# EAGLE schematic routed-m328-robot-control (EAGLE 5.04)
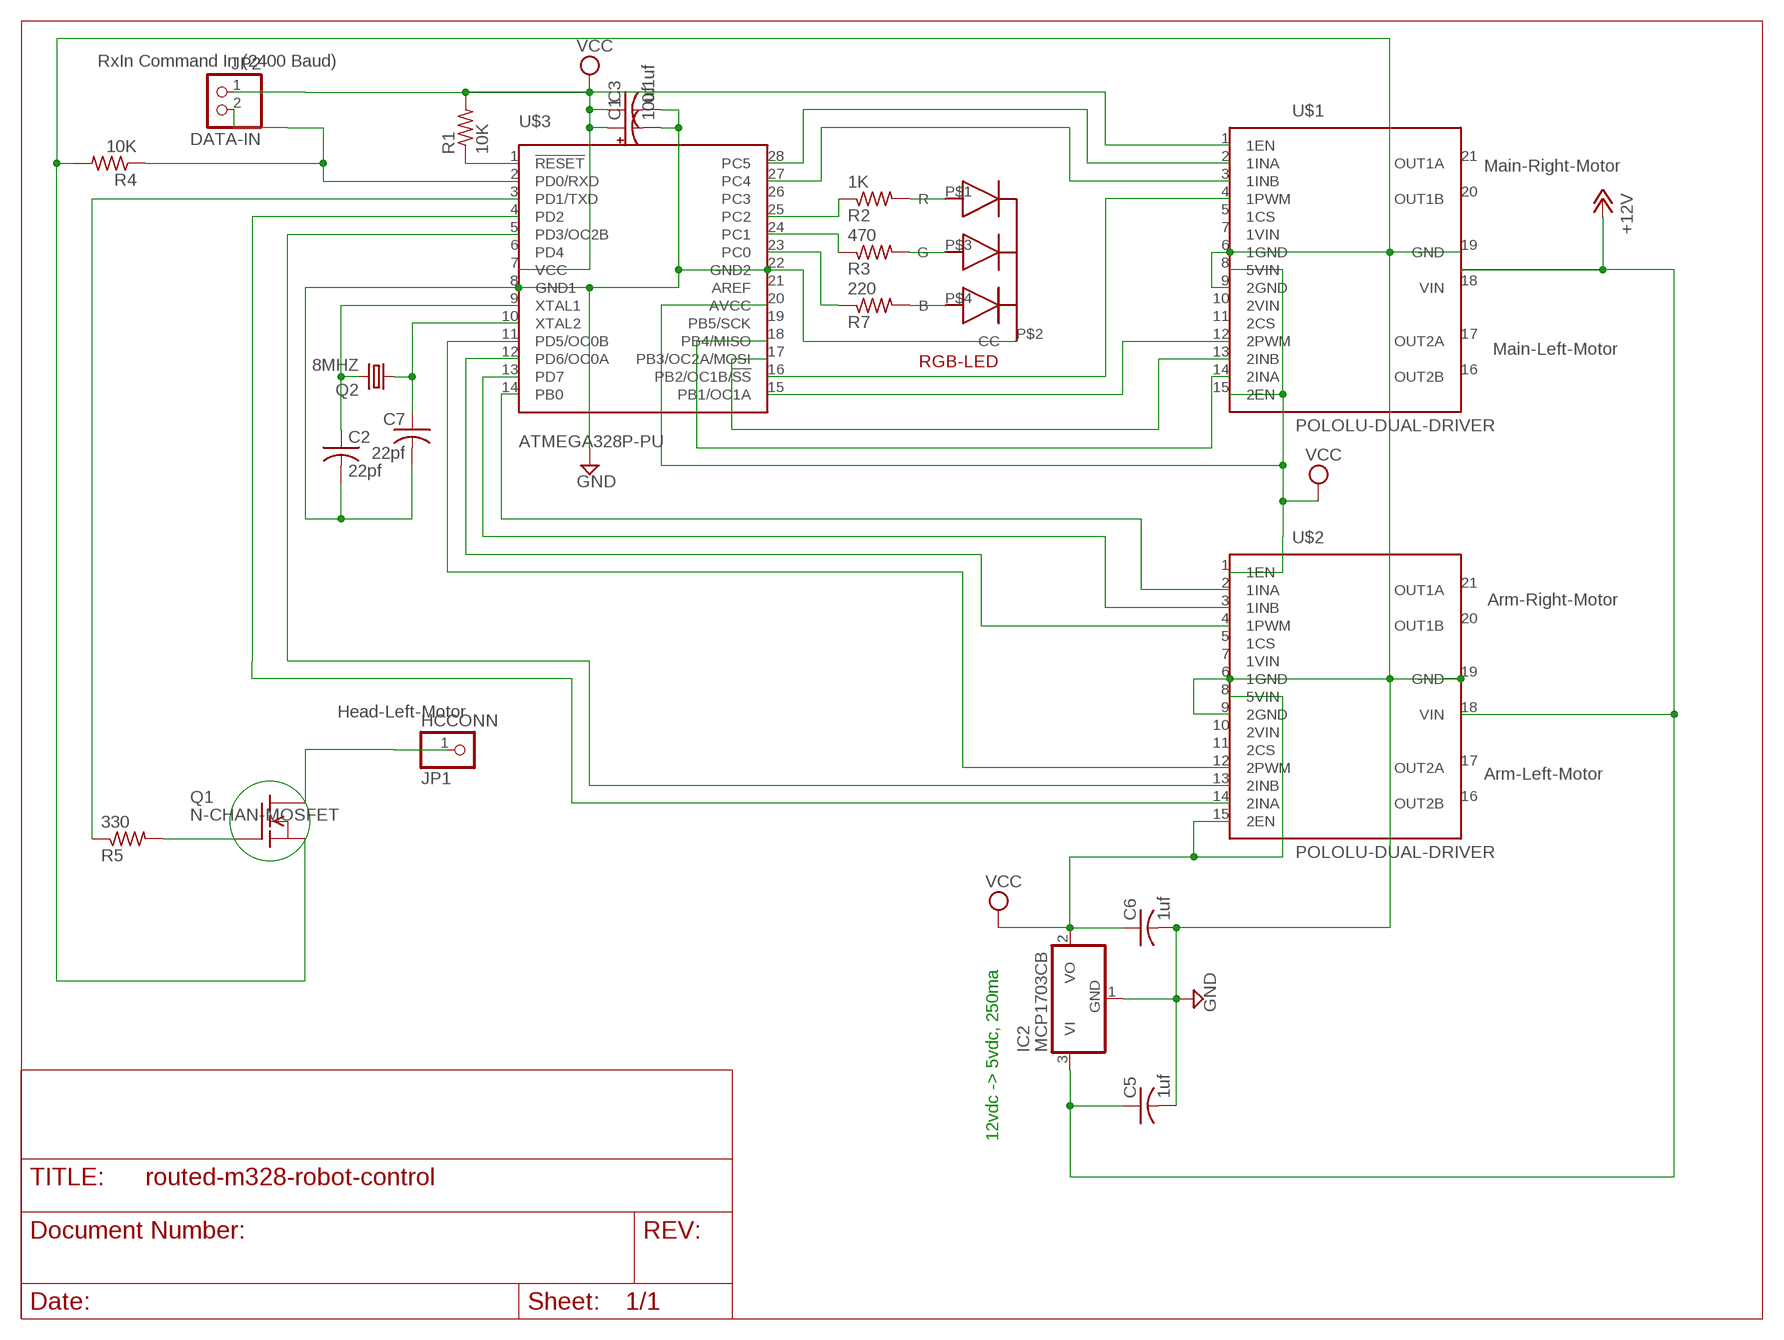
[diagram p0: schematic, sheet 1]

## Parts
C1  10uf  CPOL-USE1.8-4  [E1,8-4]
C2  22pf  C-US025-025X050  [C025-025X050]
C3  0.1uf  C-US025-025X050  [C025-025X050]
C5  1uf  C-US025-025X050  [C025-025X050]
C6  1uf  C-US025-025X050  [C025-025X050]
C7  22pf  C-US025-025X050  [C025-025X050]
IC2  MCP1703CB  [SOT23]
JP1  HCCONN  PINHD-1X1  [1X01]
JP2  DATA-IN  PINHD-1X2  [1X02]
Q1  N-CHAN-MOSFET  SUP75N06-08  [TO220]
Q2  8MHZ  CRYSTALHC49U-V  [HC49U-V]
R1  10K  R-US_0204/5  [0204/5]
R2  1K  R-US_0204/5  [0204/5]
R3  470  R-US_0204/5  [0204/5]
R4  10K  R-US_0204/5  [0204/5]
R5  330  R-US_0204/5  [0204/5]
R7  220  R-US_0204/5  [0204/5]
RGB-LED  RGB-LED-5MM  [RGB-LED-5MM]
U$1  POLOLU-DUAL-DRIVER  [POLOLU-DUAL-DRIVER]
U$2  POLOLU-DUAL-DRIVER  [POLOLU-DUAL-DRIVER]
U$3  ATMEGA328P-PU  [DIL28-3]

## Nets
+12V: C5.1 IC2.3(VI) U$2.18(VIN)
GND: C1.- C2.2 C3.2 C5.2 C6.2 C7.2 IC2.1(GND) Q1.3(S) R4.2 RGB-LED.P$2(CC) U$1.6(1GND) U$1.9(2GND) U$1.19(GND) U$2.6(1GND) U$2.9(2GND) U$2.19(GND) U$3.8(GND1) U$3.22(GND2)
N$1: R1.1 U$3.1(!RESET)
N$2: R5.1 U$3.3(PD1/TXD)
N$3: JP2.2 R4.1 U$3.2(PD0/RXD)
N$4: R7.2 RGB-LED.P$4(B)
N$5: R7.1 U$3.23(PC0)
N$6: U$2.3(1INB) U$3.13(PD7)
N$7: U$2.13(2INB) U$3.5(PD3/OC2B)
N$8: R3.2 RGB-LED.P$3(G)
N$9: R2.2 RGB-LED.P$1(R)
N$10: U$1.4(1PWM) U$3.16(PB2/OC1B/!SS)
N$11: JP1.1 Q1.2(D)
N$12: U$1.12(2PWM) U$3.15(PB1/OC1A)
N$13: U$2.12(2PWM) U$3.11(PD5/OC0B)
N$14: U$1.14(2INA) U$3.18(PB4/MISO)
N$15: U$2.4(1PWM) U$3.12(PD6/OC0A)
N$16: Q1.1(G) R5.2
N$17: R3.1 U$3.24(PC1)
N$18: R2.1 U$3.25(PC2)
N$19: U$1.13(2INB) U$3.17(PB3/OC2A/MOSI)
N$20: C7.1 Q2.1 U$3.10(XTAL2)
N$21: U$1.2(1INA) U$3.28(PC5)
N$22: U$1.3(1INB) U$3.27(PC4)
N$25: C2.1 Q2.2 U$3.9(XTAL1)
N$26: U$2.14(2INA) U$3.4(PD2)
N$54: U$2.2(1INA) U$3.14(PB0)
VCC: C1.+ C3.1 C6.1 IC2.2(VO) JP2.1 R1.2 U$1.1(1EN) U$1.8(5VIN) U$1.15(2EN) U$2.1(1EN) U$2.8(5VIN) U$2.15(2EN) U$3.7(VCC) U$3.20(AVCC)
Unconnected: U$1.5(1CS) U$1.7(1VIN) U$1.10(2VIN) U$1.11(2CS) U$1.16(OUT2B) U$1.17(OUT2A) U$1.18(VIN) U$1.20(OUT1B) U$1.21(OUT1A) U$2.5(1CS) U$2.7(1VIN) U$2.10(2VIN) U$2.11(2CS) U$2.16(OUT2B) U$2.17(OUT2A) U$2.20(OUT1B) U$2.21(OUT1A) U$3.6(PD4) U$3.19(PB5/SCK) U$3.21(AREF) U$3.26(PC3)

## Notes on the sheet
- RxIn Command In (2400 Baud)
- Main-Right-Motor
- Main-Left-Motor
- Arm-Right-Motor
- Head-Left-Motor
- Arm-Left-Motor
- 12vdc -> 5vdc, 250ma

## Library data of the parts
C1 = rcl:CPOL-US: POLARIZED CAPACITOR, American symbol
C2 C3 C5-C7 = rcl:C-US: CAPACITOR, American symbol
IC2 = linear:MCP1703: 250 mA, 16V, Low Quiescent Current LDO Regulator Source: http://ww1.microchip.com/downloads/en/DeviceDoc/22049b.pdf
JP1 = pinhead:PINHD-1X1: PIN HEADER
JP2 = pinhead:PINHD-1X2: PIN HEADER
Q1 = transistor-fet:SUP75N06-08: N-Channel Enhancement MOSFET 60V; 75A; 0,008Ohm
Q2 = crystal:CRYSTAL: CRYSTAL
R1-R5 R7 = resistor:R-US_: RESISTOR, American symbol
RGB-LED = trl:RGB-LED-5MM
U$1 U$2 = trl:POLOLU-DUAL-DRIVER
U$3 = trl:ATMEGA328P-PU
